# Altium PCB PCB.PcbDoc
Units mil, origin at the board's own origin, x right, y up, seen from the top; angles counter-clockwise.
Board outline 3000 x 3000 mil, 4 copper layers (Top Layer, MidLayer1, MidLayer2, Bottom Layer), stack 90 mil thick; 58 components, 28 nets, 153 pads, 23 vias.
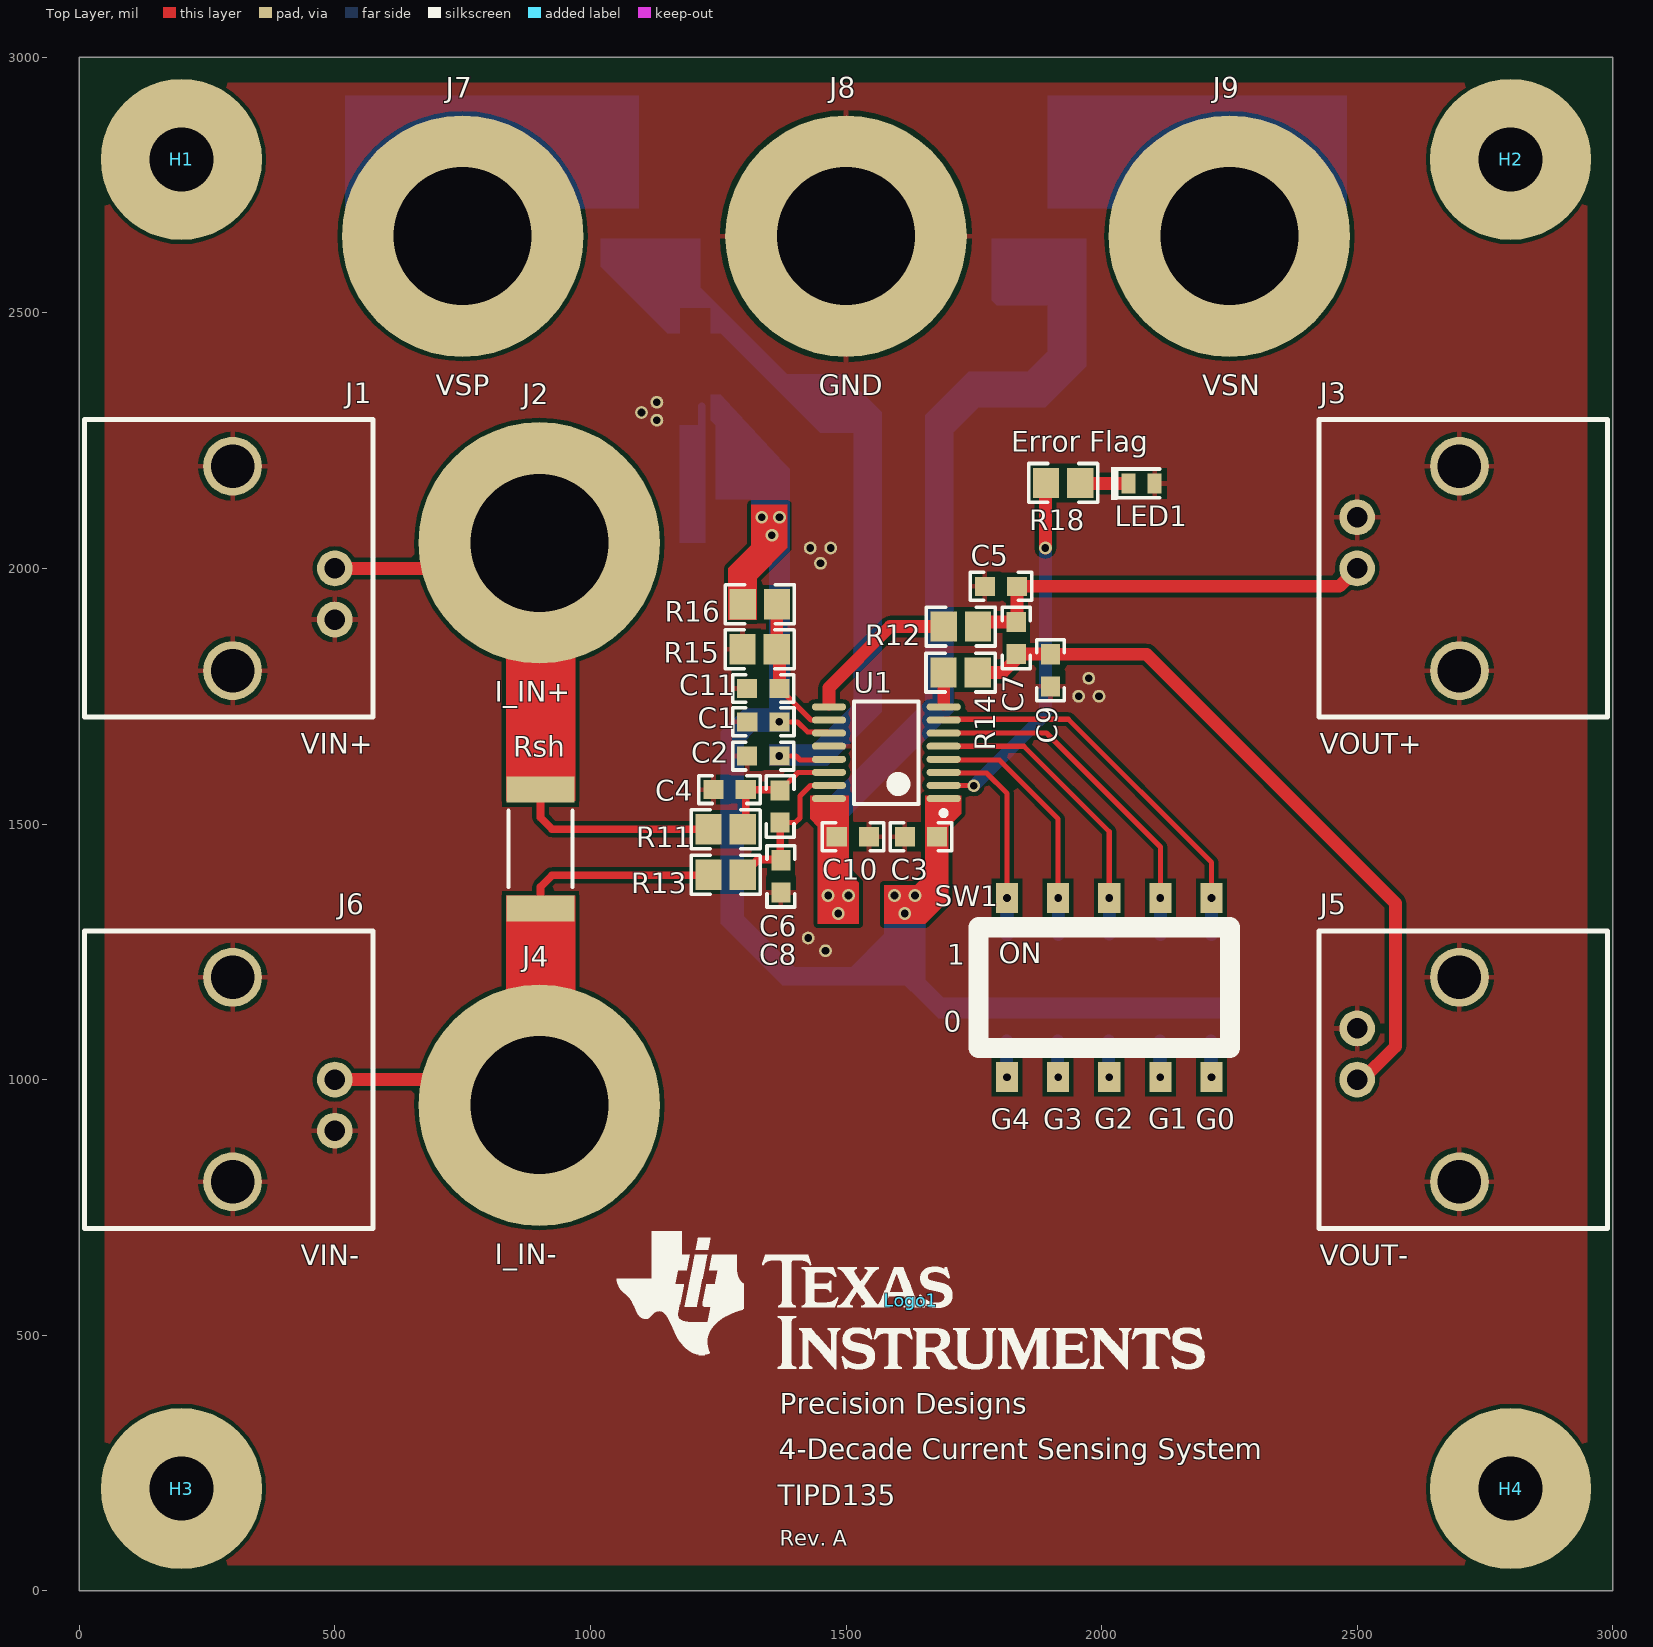
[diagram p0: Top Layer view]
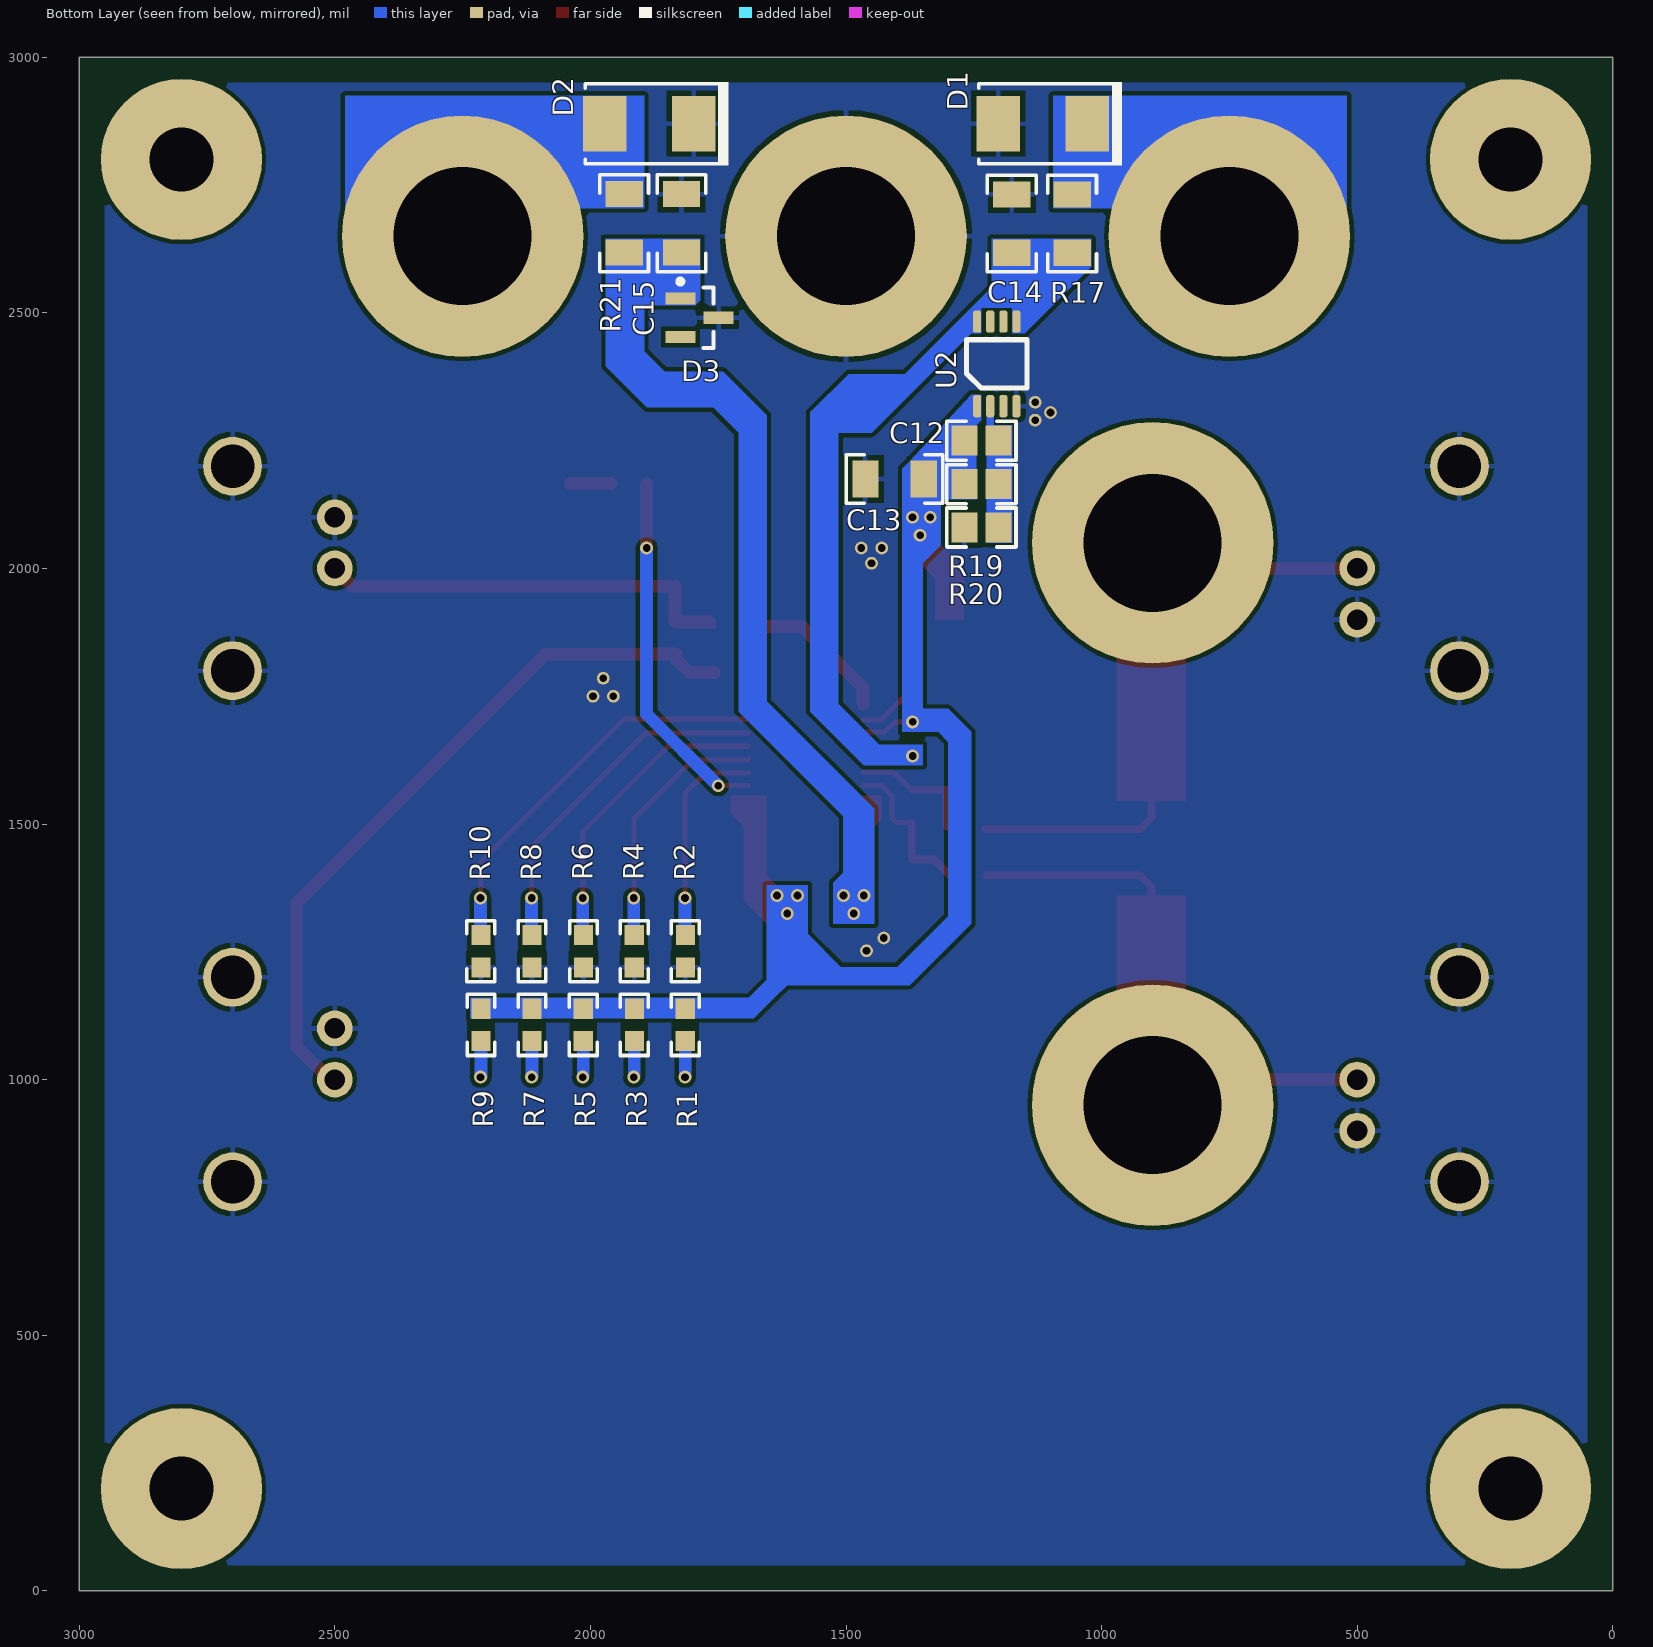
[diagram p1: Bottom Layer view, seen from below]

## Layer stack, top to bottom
Top Layer: signal copper 1.4
Dielectric: core 59.2, FR-4, Dk 4.8
MidLayer1: signal copper 1.4
Dielectric: prepreg 12.6, FR-4, Dk 4.8
MidLayer2: signal copper 1.4
Dielectric: core 12.6, FR-4, Dk 4.8
Bottom Layer: signal copper 1.4

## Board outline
0,0 3000,0 3000,3000 0,3000

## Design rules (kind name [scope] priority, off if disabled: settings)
AcuteAngle [All] p1: minimum=4.50000000000000E+0001 checktracksonly=FALSE
AssemblyTestPointUsage [All] p1: valid=2
Clearance Clearance_BoardEdge_MountingHoles [OnCopper and InComponentClass('Mounting Holes') vs IsKeepOut] p1: gap=40
Clearance Clearance_BoardEdge_Poly [OnCopper and InPoly vs IsKeepOut] p2: gap=25
Clearance Clearance_BoardEdge [OnCopper and Not InComponentClass('Logo') and not InComponentClass('FiducialMark') and not InRegion(1000,500,4000,800) vs IsKeepOut] p3: gap=75
Clearance [All] p4: gap=8
ComponentClearance ComponentClearance_Logo [InComponentClass(Logo)] p1: gap=50 collisioncheckmode=3 verticalgap=10 showdistances=FALSE
ComponentClearance ComponentClearance_ScrewToNut [(HasFootprint('NY PMS 440 0025 PH')) vs (HasFootprint('Keystone_1902C'))] p2: gap=5 collisioncheckmode=3 verticalgap=10 showdistances=FALSE
ComponentClearance ComponentClearance_MountingHoles [InComponentClass('Mounting Holes')] p3: gap=250 collisioncheckmode=3 verticalgap=100000 showdistances=FALSE
ComponentClearance ComponentClearance_SmallPassives [HasFootprint('0201*') or HasFootprint('0402*') or HasFootprint('0508') or HasFootprint('0603*') or HasFootprint('0612') or HasFootprint('0805*') or HasFootprint('0815*') or HasFootprint('0830*') or HasFootprint('1206*') or HasFootprint('1210*') or HasFootprint('1808*') or HasFootprint('1812*') or HasFootprint('1825*') or HasFootprint('2010*') or HasFootprint('2220*') or HasFootprint('2225*') or HasFootprint('2512*') or HasFootprint('2728*') or HasFootprint('3518*') vs HasFootprint('0201*') or HasFootprint('0402*') or HasFootprint('0508') or HasFootprint('0603*') or HasFootprint('0612') or HasFootprint('0805*') or HasFootprint('0815*') or HasFootprint('0830*') or HasFootprint('1206*') or HasFootprint('1210*') or HasFootprint('1808*') or HasFootprint('1812*') or HasFootprint('1825*') or HasFootprint('2010*') or HasFootprint('2220*') or HasFootprint('2225*') or HasFootprint('2512*') or HasFootprint('2728*') or HasFootprint('3518*')] p4: gap=20 collisioncheckmode=3 verticalgap=10 showdistances=FALSE
ComponentClearance ComponentClearance_THtoSMT [IsThruComponent vs IsSMTComponent] p5: gap=100 collisioncheckmode=3 verticalgap=100000 showdistances=FALSE
ComponentClearance ComponentClearance_THtoTH [IsThruComponent vs IsThruComponent] p6: gap=118.11 collisioncheckmode=3 verticalgap=100000 showdistances=FALSE
ComponentClearance [All] p7: gap=40 collisioncheckmode=3 verticalgap=10 showdistances=FALSE
DiffPairsRouting [All] p1: maxlimit=100 minlimit=10 mostfreqgap=10 maxuncoupledlength=1000
FabricationTestPointUsage TestPointUsage [All] p1: valid=2 allowmultiple=FALSE
FabricationTestpoint Testpoint [All] p1: side=3 testpointundercomponent=TRUE minsize=40 maxsize=100 preferedsize=60 minholesize=0 maxholesize=40 preferedholesize=32 testpointgrid=1 allowsidetop=TRUE allowsidebottom=TRUE usegrid=TRUE gridtolerance=0.01
FanoutControl Fanout_LCC [IsLCC] p1: bgadir=Out bgaviamode=Centered fanoutstyle=Auto fanoutdirection=Alternating viagrid=1 // Fanout_LCC (Default Rule)
FanoutControl Fanout_BGA [IsBGA] p2: bgadir=Out bgaviamode=Centered fanoutstyle=Auto fanoutdirection=Alternating viagrid=1 // Fanout_BGA (Default Rule)
FanoutControl Fanout_Default [All] p4: bgadir=Out bgaviamode=Centered fanoutstyle=Auto fanoutdirection=Alternating viagrid=1 // Fanout_Default (Default Rule)
FanoutControl Fanout_Small [(CompPinCount < 5)] p5: bgadir=Out bgaviamode=Centered fanoutstyle=Auto fanoutdirection=OutThenIn viagrid=1 // Fanout_Small (Default Rule)
HoleSize [All] p1: absolutevalues=TRUE maxlimit=300 minlimit=8 maxpercent=80.000 minpercent=20.000
MinimumAnnularRing [All] p1: minimumring=5
MinimumSolderMaskSliver MinimumSolderMaskSliver_Logo [InComponentClass('Logo') vs InComponentClass('Logo')] p1: minsoldermaskwidth=0.7
MinimumSolderMaskSliver [All] p2: minsoldermaskwidth=4
PlaneConnect [All] p1: planeconnectstyle=Relief reliefexpansion=10 reliefentries=4 reliefconductorwidth=10 reliefairgap=10
PolygonConnect "GND Vias" [(InPadClass('GND Vias') AND InNet('GND'))] p1: connectstyle=Direct reliefconductorwidth=10 reliefentries=4 polygonreliefangle="90 Angle" airgapwidth=10
PolygonConnect [All] p2: connectstyle=Relief reliefconductorwidth=10 reliefentries=4 polygonreliefangle="90 Angle" airgapwidth=10
RoutingVias [All] p1: holewidth=16 width=34 viastyle="Through Hole" minholewidth=8 minwidth=26 maxholewidth=40 maxwidth=65
SMDToCorner [All] p1: distance=30000
SilkToSilkClearance [All] p1 off: silktosilkclearance=5
SilkscreenOverComponentPads [All] p1: minsilkscreentomaskgap=5
SolderMaskExpansion [All] p1: expansion=3
Width [All] p1: maxlimit=100 minlimit=6 preferedwidth=10 checkconnectedcopper=TRUE
14 further rules are at their usual default settings.

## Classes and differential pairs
component class "Mounting Holes": H1 H2 H3 H4
component class "PGA281 SAR ADC Driver Schematic": C1 C2 C3 C4 C5 C6 C7 C8 C9 C10 C11 C12 C13 C14 C15 D1 D2 D3 J1 J2 J3 J4 J5 J6 J7 J8 J9 LED1 R1 R2 R3 R4 R5 R6 R7 R8 R9 R10 R11 R12 R13 R14 R15 R16 R17 R18 R19 R20 R21 R27 Rsh SW1 U1 U2 U3
component class Hardware_ANSI-B: H1 H2 H3 H4 Logo1
component class Logo: Logo1
pad class "GND Vias": Free-0

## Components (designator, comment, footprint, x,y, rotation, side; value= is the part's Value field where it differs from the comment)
C1 "10n" 0603 1338.23,1699.77 r0 top
C2 "10n" 0603 1338.18,1632.92 r180 top
C3 "10n" 0603 1646.79,1475.09 r0 top
C4 "1n" 0603 1272.31,1567.29 r0 top
C5 "1n" 0603 1803.26,1964.89 r0 top
C6 "10n" 0603 1371.07,1534.26 r270 top
C7 "10n" 0603 1833.02,1863.9 r270 top
C8 "1n" 0603 1372.62,1397.56 r270 top
C9 "1n" 0603 1899.98,1800.7 r270 top
C10 "10n" 0603 1513.52,1475.09 r180 top
C11 "10n" 0603 1338.16,1765.16 r180 top
C12 "10n" 0805 1235,2250 r180 bottom
C13 "10u" 1206 1405,2175 r0 bottom
C14 "10u" 1206 1175.68,2674.61 r90 bottom
C15 "10u" 1206 1821.87,2675.22 r270 bottom
D1 "SMBJ24CA" SMB 1115,2870 r0 bottom
D2 "SMBJ24CA" SMB 1885,2870 r0 bottom
D3 "BAS70-TP" DBZ0003A_N 1786.64,2490.31 r180 bottom
H1 "NY PMS 440 0025 PH" "NY PMS 440 0025 PH" 200,2800 r0 top
H2 "NY PMS 440 0025 PH" "NY PMS 440 0025 PH" 2800,2800 r0 top
H3 "NY PMS 440 0025 PH" "NY PMS 440 0025 PH" 200,200 r0 top
H4 "NY PMS 440 0025 PH" "NY PMS 440 0025 PH" 2800,200 r0 top
J1 "VIN+" "Right Angle BNC" 500,2000 r90 top
J2 "I_IN+" Johnson_108-0740-001 900,2050 r0 top
J3 "VOUT+" "Right Angle BNC" 2500,2000 r270 top
J4 "I_IN-" Johnson_108-0740-001 900,950 r0 top
J5 "VOUT-" "Right Angle BNC" 2500,1000 r270 top
J6 "VIN-" "Right Angle BNC" 500,1000 r90 top
J7 "VSP" Johnson_108-0740-001 750,2650 r0 top
J8 "GND" Johnson_108-0740-001 1500,2650 r0 top
J9 "VSN" Johnson_108-0740-001 2250,2650 r0 top
LED1 "LTST-C190CKT" Diode_0603 2078.11,2166.17 r0 top
Logo1 "Texas Instruments" TI_Stacked_Overlay_Medium 1626.78,568.73 r0 top
R1 "Used in BOM report" 0603 1814.36,1107.11 r270 bottom
R2 "Used in BOM report" 0603 1814.32,1251.11 r270 bottom
R3 "Used in BOM report" 0603 1914.08,1107.11 r270 bottom
R4 "Used in BOM report" 0603 1914.34,1251.11 r270 bottom
R5 "Used in BOM report" 0603 2014.08,1107.11 r270 bottom
R6 "Used in BOM report" 0603 2013.5,1251.11 r270 bottom
R7 "Used in BOM report" 0603 2114.32,1107.11 r270 bottom
R8 "Used in BOM report" 0603 2114.36,1251.11 r270 bottom
R9 "Used in BOM report" 0603 2214.08,1107.11 r270 bottom
R10 "Used in BOM report" 0603 2214.38,1251.11 r270 bottom
R11 "Used in BOM report" 0805 1264.55,1489.72 r0 top
R12 "Used in BOM report" 0805 1724.66,1886.28 r0 top
R13 "Used in BOM report" 0805 1264.55,1400.76 r0 top
R14 "Used in BOM report" 0805 1724.14,1796.3 r0 top
R15 "Used in BOM report" 0805 1331.1,1842.01 r0 top
R16 "Used in BOM report" 0805 1331.54,1930 r0 top
R17 "Used in BOM report" 1206 1057.56,2674.61 r270 bottom
R18 "Used in BOM report" 0805 1924.92,2167.18 r0 top
R19 "Used in BOM report" 0805 1235,2165 r0 bottom
R20 "Used in BOM report" 0805 1235,2080 r0 bottom
R21 "Used in BOM report" 1206 1933.93,2675.22 r270 bottom
Rsh "Used in BOM report" 2512 902.43,1451.11 r90 top
SW1 "Used in BOM report" A6S-5104-H 2015,1180 r90 top
U1 "PGA281" PW0016A_N 1578.88,1639.39 r180 top
U2 "TPS7A4101" dgk-8 1205,2400 r90 bottom

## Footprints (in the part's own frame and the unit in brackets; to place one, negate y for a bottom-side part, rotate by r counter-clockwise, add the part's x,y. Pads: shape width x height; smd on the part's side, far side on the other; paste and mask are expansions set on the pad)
0603 [mm] "0603 from SM-752 data"
  rect 1x0.95 smd: 1(-0.8,0) 2(0.8,0)
  silkscreen extent -1.52,-0.69 1.52,0.69, body extent -0.87,-0.47 0.87,0.47, height 0.85
0805 [mm] "0805 from SM-752 data"
  rect 1.3x1.5 smd: 1(-0.85,0) 2(0.85,0)
  silkscreen extent -1.72,-0.97 1.72,0.97, body extent -1.1,-0.72 1.1,0.72, height 1.1
1206 [mm] "1206 from SM-752 data"
  rect 1.3x1.85 smd: 1(-1.45,0) 2(1.45,0)
  silkscreen extent -2.4,-1.21 2.4,1.21, body extent -1.7,-0.9 1.7,0.9, height 1.35
2512 [mm] "Chip Resistor, Body 6.3x3.2mm, IPC Medium Density"
  rect 1.3x3.4 smd: 1(-2.95,0) 2(2.95,0)
  silkscreen extent -1.9,-1.6 1.9,1.6, body extent -3.22,-1.67 3.22,1.67, height 0.71
A6S-5104-H [mm]
  rect 1.5x1.1 smd: 1(-4.45,5.08) 2(-4.45,2.54) 3(-4.45,0) 4(-4.45,-2.54) 5(-4.45,-5.08) 6(4.45,-5.08) 7(4.45,-2.54) 8(4.45,0) 9(4.45,2.54) 10(4.45,5.08)
  silkscreen extent -3,-6 3,6.5
DBZ0003A_N [mm] "SOT23, 3-Leads, Body 2.9x1.3mm, Pitch 0.95mm, Lead Span 2.4mm, IPC Medium Density"
  rect 1.5x0.6 smd: 1(-0.95,0.95) 2(-0.95,-0.95) 3(0.95,0)
  silkscreen extent -1.07,-1.5 0.7,1.92, body extent -0.7,-1.52 0.7,1.52, height 1.12
dgk-8 [mm] "MSOP-8, SMD, 0.65mm PITCH"
  rrect50% 1.1x0.4 smd mask+0.05: 1(-2.1,0.975) 2(-2.1,0.325) 3(-2.1,-0.325) 4(-2.1,-0.975) 5(2.1,-0.975) 6(2.1,-0.325) 7(2.1,0.325) 8(2.1,0.975)
  silkscreen extent -1.2,-1.5 1.2,1.5
Diode_0603 [mm] "Based on Bourns recommended land pattern Rev 10/09"
  rect 0.7x1 smd: 1(-0.65,0) 2(0.65,0)
  silkscreen extent -1.5,-0.8 0.9,0.8, body extent -0.9,-0.5 0.9,0.5, height 0.85
Johnson_108-0740-001 [mm] "Banana Jack Uninsulated Standard Type"
  round 12 hole 6.858: 1(0,0)
  body extent -4.77,-5.43 4.75,5.57, height 2.39
"NY PMS 440 0025 PH" [mm] "4-40 nylon screw and mounting hole"
  round 8 hole 3.2: 1(0,0)
  body extent -3.3,-3.3 3.3,3.3, height 2.69
PW0016A_N [mm] "TSOP, 16-Leads, Body 5x4.4mm, Pitch 0.65mm, IPC Medium Density"
  oval 1.7x0.35 smd: 1(-2.85,2.275) 2(-2.85,1.625) 3(-2.85,0.975) 4(-2.85,0.325) 5(-2.85,-0.325) 6(-2.85,-0.975) 7(-2.85,-1.625) 8(-2.85,-2.275) 9(2.85,-2.275) 10(2.85,-1.625) 11(2.85,-0.975) 12(2.85,-0.325) 13(2.85,0.325) 14(2.85,0.975) 15(2.85,1.625) 16(2.85,2.275)
  silkscreen extent -2.98,-2.55 1.6,3.12, body extent -2.25,-2.55 2.25,2.55, height 1.2
"Right Angle BNC" [mil]
  round 70 hole 40: 1(0,0) 2(-100,0)
  round 115 hole 85: 3(200,200) 4(-200,200)
  silkscreen extent -291,-75 291,490, body extent -290,-50 291,1325, height 519
SMB [mil] "Molded Diode, 2-Leads, Body 5.4x3.6mm, IPC Medium Density, based on OnSemi component dimensions"
  rect 85x107.99 smd: 1(-87.01,0) 2(87.01,0)
  silkscreen extent -155,-82 125,82, body extent -106,-71 106,71, height 91
TI_Stacked_Overlay_Medium [mil]
  silkscreen extent -576,-136 576,134

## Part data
C1 C2 C3 C4 C5 C6 C7 C8 C9 C10 C11 C12 C13 C14 C15: library part Capacitor, "CAP, CERM, xxxF, xxV, [TempCo], xx%, [PackageReference]"
D1 D2: library part TVS_BI_SMB
H1 H2 H3 H4: "Machine Screw, Round, #4-40 x 1/4, Nylon, Philips panhead"
J1 J3 J5 J6: library part "BNC Right Angle"
J2 J4 J7 J8 J9: library part 108-0740-001, "Standard Banana Jack, Uninsulated, 15A"
LED1: library part LED, "LED, [Color], [MountType]"
Logo1: library part TI_Logo, "Texas Instrument Corporate Signature"
R1 R2 R3 R4 R5 R6 R7 R8 R9 R10 R11 R12 R13 R14 R15 R16 R17 R18 R19 R20 R21 Rsh: library part Resistor, "RES, xxx ohm, x%, xW, [PackageReference]"
SW1: library part SWITCH_5xSPST

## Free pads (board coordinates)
  round 25 hole 15: 0(1100,2305) 0(1130,2290) 0(1130,2325) 0(1426,1277) 0(1430,2040) 0(1450,2010) 0(1460,1252) 0(1470,2040) 0(1955,1750) 0(1975,1785) 0(1995,1750)

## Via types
v1: diameter 25, hole 15, Top Layer to Bottom Layer, 23 vias

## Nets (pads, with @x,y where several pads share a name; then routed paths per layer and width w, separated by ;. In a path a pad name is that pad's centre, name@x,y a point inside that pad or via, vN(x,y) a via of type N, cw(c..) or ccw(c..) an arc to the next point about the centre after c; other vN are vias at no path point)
/EF: R18.1 U1.2 | length 709.9
  Top Layer w10: U1.2 1749.59,1575.41 v1(1750,1575) ; R18.1@1890,2165.72 R18.1
  Top Layer w25: v1(1890,2040) R18.1@1890,2165.72
  Bottom Layer w25: v1(1750,1575) 1890,1715 v1(1890,2040)
G0: R10.1 SW1.6 U1.7 | length 783.2
  Top Layer w10: U1.7 1692.72,1705 1935,1705 2215,1425 v1(2215,1355.2)
  Bottom Layer w10: R10.1 R10.1@2215,1283.23
  Bottom Layer w25: R10.1@2215,1283.23 v1(2215,1355.2)
G1: R8.1 SW1.7 U1.6 | length 688.8
  Top Layer w10: U1.6 1892.23,1677.77 2115,1455 v1(2115,1355.2)
  Bottom Layer w10: R8.1 R8.1@2115,1283.25
  Bottom Layer w25: R8.1@2115,1283.25 v1(2115,1355.2)
G2: R6.1 SW1.8 U1.5 | length 596.2
  Top Layer w10: U1.5 1847.82,1652.18 2015,1485 v1(2015,1355.2)
  Bottom Layer w10: R6.1 R6.1@2015,1284.11
  Bottom Layer w25: R6.1@2015,1284.11 v1(2015,1355.2)
G3: R4.1 SW1.9 U1.4 | length 499.9
  Top Layer w10: U1.4 1692.68,1625 1800,1625 1915,1510 v1(1915,1355.2)
  Bottom Layer w10: R4.1 R4.1@1915,1283.27
  Bottom Layer w25: R4.1@1915,1283.27 v1(1915,1355.2)
G4: R2.1 SW1.10 U1.3 | length 418.6
  Top Layer w10: U1.3 1692.09,1600 1775,1600 1815,1560 v1(1815,1355.2)
  Bottom Layer w10: R2.1 R2.1@1815,1283.29
  Bottom Layer w25: R2.1@1815,1283.29 v1(1815,1355.2)
GND: C1.1 C2.2 C3.1 C4.1 C5.1 C8.2 C9.2 C10.1 C11.2 C13.2 C14.2 C15.1 D1.2 D2.1 D3.3 J1.2 J1.3 J1.4 J3.2 J3.3 J3.4 J5.2 J5.3 J5.4 J6.2 J6.3 J6.4 J8.1 LED1.2 pad.0 R2.2 R4.2 R6.2 R8.2 R10.2 R15.1 R20.2 U1.12 U2.4
NetC4_2: C4.2 C6.1 R11.2 U1.14 | length 258.1
  Top Layer w10: R11.2 R11.2@1303.81,1495.51 ; C6.1@1369.54,1567.29 C6.1 1406.31,1601 U1.14
  Top Layer w15: R11.2@1303.81,1495.51 C4.2 C6.1@1369.54,1567.29
NetC5_2: C5.2 C7.1 J3.1 R12.2 | length 828.7
  Top Layer w10: R12.2 R12.2@1767.23,1895.4 ; C7.1 C7.1@1834.76,1897.14
  Top Layer w25: R12.2@1767.23,1895.4 C7.1 ; C7.1@1834.76,1897.14 C5.2 2464.89,1964.89 J3.1
NetC6_2: C6.2 C8.1 R13.2 U1.15 | length 308.5
  Top Layer w10: C6.2 1400.84,1502.77 1410,1511.93 1410,1555 1430.41,1575.41 U1.15
  Top Layer w15: R13.2 1327.86,1430.6 1371.07,1430.6 C6.2
NetC7_2: C7.2 C9.1 J5.1 R14.2 | length 1425.8
  Top Layer w10: C9.1@1899.77,1832.4 C9.1 ; J5.1 J5.1@2505,995
  Top Layer w25: R14.2 1806.3,1796.3 1833.02,1823.02 C7.2 C9.1@1899.77,1832.4 ; C9.1 2087.81,1832.19 2575,1345 2575,1065 J5.1@2505,995
NetC11_1: C11.1 R15.2 R16.2 U1.10 | length 290
  Top Layer w10: R15.2 1364.56,1825.44 R15.2@1370,1820 ; R16.2@1364.56,1929.56 R16.2 ; C11.1@1370,1765.51 C11.1 1431.46,1703.36 U1.10
  Top Layer w25: R15.2 R16.2@1364.56,1929.56 ; C11.1@1370,1765.51 R15.2@1370,1820
NetC12_2: C12.2 R19.1 R20.1 U2.2 | length 74.1
  Bottom Layer w10: C12.2 C12.2@1217.8,2266.26
  Bottom Layer w15: C12.2@1217.8,2266.26 U2.2
NetD1_1: D1.1 J7.1 R17.1
NetD2_2: D2.2 J9.1 R21.1
NetJ1_1: J1.1 J2.1 R11.1 Rsh.2 | length 810
  Top Layer w10: J2.1@850,2000 J2.1
  Top Layer w15: Rsh.2 902.43,1512.57 925,1490 R11.1@1227.69,1490
  Top Layer w25: J1.1 J2.1@850,2000
NetJ4_1: J4.1 J6.1 R13.1 Rsh.1 | length 814.1
  Top Layer w10: J4.1@850,1000 J4.1 ; Rsh.1 Rsh.1@913.26,1324.14 ; R13.1@1224.92,1400 R13.1@1227.63,1397.3
  Top Layer w15: Rsh.1 902.43,1377.43 925,1400 R13.1@1224.92,1400
  Top Layer w25: J6.1 J4.1@850,1000
NetLED1_1: LED1.1 R18.2 | length 81
  Top Layer w10: R18.2 R18.2@1959.39,2166.17
  Top Layer w25: R18.2@1959.39,2166.17 LED1.1@2039,2166.17
NetR1_2: R1.2 SW1.1 | length 71.1
  Bottom Layer w10: v1@1814.36,1005.44 v1(1815,1004.8)
  Bottom Layer w25: v1@1814.36,1005.44 R1.2
NetR3_2: R3.2 SW1.2 | length 71.2
  Bottom Layer w10: v1@1914.08,1005.72 v1(1915,1004.8)
  Bottom Layer w25: v1@1914.08,1005.72 R3.2
NetR5_2: R5.2 SW1.3 | length 71.2
  Bottom Layer w10: v1@2014.08,1005.72 v1(2015,1004.8)
  Bottom Layer w25: v1@2014.08,1005.72 R5.2
NetR7_2: R7.2 SW1.4 | length 71.1
  Bottom Layer w10: v1@2114.32,1005.48 v1(2115,1004.8)
  Bottom Layer w25: v1@2114.32,1005.48 R7.2
NetR9_2: R9.2 SW1.5 | length 71.2
  Bottom Layer w10: v1@2214.08,1005.72 v1(2215,1004.8)
  Bottom Layer w25: v1@2214.08,1005.72 R9.2
NetR12_1: R12.1 U1.9 | length 305.7
  Top Layer w25: U1.9@1466.68,1735 1466.68,1766.68 1586.28,1886.28 R12.1
NetR14_1: R14.1 U1.8 | length 61.5
  Top Layer w10: R14.1 R14.1@1691.09,1795.88
  Top Layer w25: U1.8@1691.09,1735 R14.1@1691.09,1795.88
VSN: C10.2 C15.2 D3.1 R21.2 U1.16 | length 193.2
  Top Layer w10: U1.16 1466.68,1528.32 1480,1515 1480,1477.11 C10.2
  Bottom Layer w50: C15.2 R21.2
  other v1: 1485,1325 1465,1360 1505,1360
VSOP: C1.2 C3.2 C12.1 C13.1 R1.1 R3.1 R5.1 R7.1 R9.1 R16.1 R19.2 U1.1 U1.11 U2.1 | length 585.8
  Top Layer w10: v1(1369.73,1699.77) 1405.23,1699.77 1425,1680 1464.45,1680 U1.11 ; C3.2 1680,1476.8 1680,1520 1691.09,1531.09 U1.1
  Bottom Layer w25: R1.1 R3.1 R5.1 R7.1 R9.1
  other v1: 1615,1325 1595,1360 1635,1360 1355,2065 1335,2100 1370,2100
VSP: C2.1 C14.1 R17.2 U1.13 U2.5 U2.8 | length 219.1
  Top Layer w10: v1(1369.68,1632.92) 1402.08,1632.92 1410,1625 1465.09,1625 U1.13
  Bottom Layer w50: R17.2 C14.1
pads on no net: D3.2 H1.1 H2.1 H3.1 H4.1 U2.3 U2.6 U2.7

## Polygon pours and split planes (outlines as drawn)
GND on Top Layer "Bottom Layer-No Net" (solid, remove dead copper, pour order 6): 50,50 2950,50 2950,2950 50,2950
GND on Bottom Layer "Bottom Layer-No Net 1" (solid, remove dead copper, pour order 8): 50,50 2950,50 2950,2950 50,2950

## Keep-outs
Keep-Out Layer:
  text ".Layer_Name" at 577,-858.49 h30

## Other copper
Top Layer:
  region net VSN: 1525,1305 1525,1385 1505,1405 1505,1555 1430,1555 1430,1510 1445,1495 1445,1305
  region net VSOP: 1655,1495 1655,1555 1725,1555 1725,1520 1700,1495
  region net VSOP: 1575,1380 1635,1380 1655,1400 1655,1495 1700,1495 1700,1350 1655,1305 1575,1305
  region net VSOP: 1270,1900 1325,1900 1325,1980 1385,2040 1385,2125 1315,2125 1315,2045 1270,2000
  region net NetJ4_1: 835,1360 970,1360 970,1135 835,1135
  region net NetJ1_1: 835,1545 970,1545 970,1830 835,1830
Bottom Layer:
  region net VSOP: 1655,1305 1655,1195 1600,1250
  region net VSOP: 1575,1225 1680,1120 2235,1120 2235,1160 1690,1160 1600,1250 1590,1250 1590,1240
  region net VSOP: 1319.88,1680 1300,1660.12 1300,1320 1400,1220 1510,1220 1575,1285 1575,1380 1655,1380 1655,1305 1615,1185 1375,1185 1255,1305 1255,1680 1300,1725 1390,1725 1390,1680
  region net VSN: 1445,1385 1445,1530 1655,1740 1655,2300 1740,2385 1855,2385 1895,2425 1895,2645 1970,2645 1970,2395 1890,2315 1760,2315 1710,2265 1710,1720 1505,1515 1505,1405 1525,1385
  region net VSN: 1445,1305 1525,1305 1525,1385 1445,1385
  region net VSP: 1495,2380 1570,2305 1570,2265 1450,2265 1335,2380
  region net VSP: 1350,1655 1435,1655 1515,1735 1515,2285 1520,2280 1570,2280 1570,1720 1465,1615 1350,1615
  region net VSP: 1350,1615 1350,1655 1390,1655 1390,1615
  region net VSP: 1255,2510 1470,2295 1570,2295 1570,2265 1450,2265 1250,2465 1250,2510
  region net VSOP: 1315,2045 1350,2010 1350,1680 1390,1680 1390,2195 1385,2200 1315,2130
  region net VSOP: 1375,2210 1385,2200 1385,2045 1315,2045 1315,2210
  region net VSOP: 1235,2340 1235,2290 1245,2280 1245,2135 1375,2135 1375,2210 1255,2340
  region net NetC12_2: 1175,2280 1225,2280 1225,2050 1175,2050
  region net VSP: 1235,2510 1235,2460 1255,2460 1255,2510 1215,2550 1175,2510
  region net VSP: 1175,2460 1175,2510 1215,2550 1215,2645 1020,2645 1020,2590 1150,2460
  region net VSN: 1795,2515 1785,2525 1785,2645 1970,2645 1970,2590 1895,2515
  region net NetD2_2: 1895,2705 1895,2925 2480,2925 2480,2705
  region net NetD1_1: 520,2925 1095,2925 1095,2705 520,2705

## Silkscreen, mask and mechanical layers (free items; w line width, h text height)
Top Overlay:
  text "Error Flag" at 1823,2228 h40
  text "1" at 1697.77,1224.27 h40
  text "0" at 1690.86,1093.19 h40
  text "G2" at 1985.63,904.31 h40
  text "G1" at 2091.09,903.78 h40
  text "G4" at 1783.2,903.25 h40
  text "G3" at 1886.01,903.25 h40
  text "G0" at 2184.36,903.25 h40
  text "Precision Designs" at 1370.87,346.16 h40
  text "4-Decade Current Sensing System" at 1367.99,257.02 h40
  text "TIPD135" at 1366.97,166.83 h40
  text "Rev. A" at 1370.56,87.96 h30
Top Paste:
  text ".Layer_Name" at 577,-858.49 h30
Bottom Paste:
  text ".Layer_Name" at 577,-858.49 h30
Top Solder:
  text ".Layer_Name" at 577,-858.49 h30
  text ".Layer_Name" at 577,-858.49 h30
Bottom Solder:
  text ".Layer_Name" at 577,-858.49 h30
Drill Guide:
  text ".Layer_Name" at 577,-858.49 h30
M1 Board Outline:
  the board outline again, w10
M2 Board Dimensions:
  rectangle: 124.5,-410.5 499.5,-285.5
  rectangle: -0.5,-285.5 124.5,-160.5
  lines w7: -0.5,-285.5 999.5,-285.5 ; 124.5,-410.5 124.5,-160.5 ; 249.5,-410.5 249.5,-160.5 ; 499.5,-410.5 499.5,-160.5 ; 749.5,-410.5 749.5,-160.5 ; -0.5,-410.5 -0.5,-160.5 999.5,-160.5 999.5,-410.5 -0.5,-410.5
  lines w10: -0.5,-475.5 -0.5,-455.5 ; 59.5,-485.5 -0.5,-465.5 ; 59.5,-445.5 -0.5,-465.5 ; 223.58,-465.5 -0.5,-465.5 ; 775.42,-465.5 999.5,-465.5 ; 939.5,-485.5 999.5,-465.5 ; 939.5,-445.5 999.5,-465.5 ; 999.5,-475.5 999.5,-455.5
  text "1000 (mil)" at 233.58,-501.49 h60
M3 3D STEP Top:
  text ".Layer_Name" at 577,-858.49 h30
M4 3D STEP Bottom:
  text ".Layer_Name" at 577,-858.49 h30
M5 Assembly Top:
  lines w10: -292,-930.17 6308,-930.17 ; -292,-726.83 6310,-726.83 ; -292,-523.5 -292,-1133.5 3713,-1133.5 6310,-1133.5 6310,-523.5 -291.5,-523.5 -291.5,-1133.5 1284,-1133.5 ; 2173,-1133.5 2173,-523.5 ; 3440,-726.83 3440,-523.5 ; 4280,-726.83 4280,-523.5 ; 4902,-1140 4902,-937.17
  text "COMPONENTS MARKED 'DNP' SHOULD NOT BE POPULATED, AND MAY NOT BE IN BILL OF MATERIALS" at 1153.5,-318.5 h30
  text "ASSEMBLY VARIANT:" at 1153,-434 h30
  text ".VariantName" at 2189,-434 h30
  text "PCB VIEWED FROM TOP SIDE" at -228.5,-655.67 h30
  text "BOARD #:" at 2248,-655.67 h30
  text ".PRJ_Number" at 2793.5,-655.67 h30
  text "REV:" at 3638,-655.67 h30
  text ".PCB_Rev" at 3929.5,-655.67 h30
  text "SVN REV:" at 4476,-655.67 h30
  text ".VersionControl_RevNumber" at 4982,-655.67 h30
  text "IGNORE ->" at -228.5,-858.49 h30
  text "PLOT NAME =" at -228.5,-1064.34 h30
  text ".plot_File_Name" at 577,-1064.34 h30
  text "GENERATED    :" at 2250,-1064.34 h30
  text ".Print_Date" at 3119.5,-1064.34 h30
  text ".Print_Time" at 3848.5,-1064.34 h30
  text "TEXAS INSTRUMENTS" at 5113,-1064.34 h30
M6 Assembly Bottom:
  lines w10: -292.5,-727.33 6309.5,-727.33 ; -290.5,-930.67 6309.5,-930.67 ; 1115.5,-1140.5 1115.5,-937.67 ; 1737.5,-727.33 1737.5,-524 ; 2577.5,-727.33 2577.5,-524 ; 3844.5,-1134 3844.5,-524 ; 4733.5,-1134 6309,-1134 6309,-524 -292.5,-524 -292.5,-1134 2304.5,-1134 6309.5,-1134 6309.5,-524 ; 963,2590 963,2709.06 963.94,2710 1049,2710 1057.24,2701.76 1057.24,2591 1056.24,2590 963,2590
  text "COMPONENTS MARKED 'DNP' SHOULD NOT BE POPULATED, AND MAY NOT BE IN BILL OF MATERIALS" at 6102,-318 h30
  text ".VariantName" at 5058,-434 h30
  text "ASSEMBLY VARIANT:" at 6097,-434 h30
  text ".VersionControl_RevNumber" at 1035.5,-656.17 h30
  text "SVN REV:" at 1541.5,-656.17 h30
  text ".PCB_Rev" at 2088,-656.17 h30
  text "REV:" at 2379.5,-656.17 h30
  text ".PRJ_Number" at 3224,-656.17 h30
  text "BOARD #:" at 3769.5,-656.17 h30
  text "PCB VIEWED FROM BOTTOM SIDE" at 6246,-656.17 h30
  text "IGNORE ->" at 2547.85,-858.49 h30
  text "TEXAS INSTRUMENTS" at 904.5,-1064.84 h30
  text ".Print_Time" at 2169,-1064.84 h30
  text ".Print_Date" at 2898,-1064.84 h30
  text "GENERATED    :" at 3767.5,-1064.84 h30
  text ".plot_File_Name" at 5440.5,-1064.84 h30
  text "PLOT NAME =" at 6246,-1064.84 h30
M9 Title Sheet:
  drawing of 57 lines, arcs and shapes, not listed
  text "1" at 739.84,8036.5 h30
  text "2" at 3235.5,8036.5 h30
  text "3" at 5724.84,8036.5 h30
  text "4" at 8231.51,8036.5 h30
  text "5" at 10730.5,8036.5 h30
  text "6" at 13235.5,8036.5 h30
  text "A" at -416.5,6893.5 h30
  text "A" at 14383.5,6893.5 h30
  text "B" at -416.5,4513.5 h30
  text "B" at 14383.5,4513.5 h30
  text "C" at -416.5,2138.5 h30
  text "C" at 14383.5,2138.5 h30
  text "PROJECT TITLE:" at 11343.5,277.5 h30
  text ".PRJ_Title" at 11393.5,144.17 h30
  text "DESIGNED FOR:" at 11343.5,-23.5 h30
  text ".PRJ_Customer" at 11393.5,-163.5 h30
  text "D" at -416.5,-231.5 h30
  text "D" at 14383.5,-231.5 h30
  text "FILE NAME:" at 11343.5,-323.5 h30
  text ".PCB_File_Name_No_Path" at 11393.5,-443.5 h30
  text "Texas Instruments (TI) and/or its licensors do not warrant the accuracy or completeness of this specification" at 6374,-605.34 h30
  text "ENGINEER:" at 11343.5,-613.5 h30
  text "LAYOUT BY:" at 12848.5,-613.5 h30
  text "or any information contained therein. TI and/or its licensors do not warrant that this design will meet" at 6329.01,-718 h30
  text ".PRJ_Engineer" at 11393.5,-768.49 h30
  text ".PCB_Layout" at 12899,-768.49 h30
  text "the specifications, will be suitable for your application or fit for any particular purpose, or will operate in" at 6329.01,-830.67 h30
  text ".Layer_Name" at 577,-858.49 h30
  text "ALTIUM DESIGNER VERSION:" at 12848.5,-923.5 h30
  text "an implementation. TI and/or its licensors do not warrant that the design is production worthy. You should" at 6329.01,-943.33 h30
  text "completely validate and test your design implementation to confirm the system functionality for your application." at 6374,-1056 h30
  text ".print_Scale" at 11393.5,-1056.83 h30
  text ".Application_BuildNumber" at 12899,-1056.83 h30
  text "1" at 739.84,-1263.5 h30
  text "2" at 3235.5,-1263.5 h30
  text "3" at 5724.84,-1263.5 h30
  text "4" at 8231.51,-1263.5 h30
  text "5" at 10730.5,-1263.5 h30
  text "6" at 13235.5,-1263.5 h30
M10 Fab Notes:
  drawing of 203 lines, arcs and shapes, not listed
  text "DESIGN INFORMATION" at 12381.02,6810 h30
  text "(REFER ALSO ARRAY/PANEL PROFILING INFORMATION)" at 12019.46,6648.29 h30
  text "BOARD SIZE" at 11333.46,6644 h30
  text "3450MIL" at 11795.78,6516.18 h30
  text "X" at 12301.46,6516.18 h30
  text "4950MIL" at 12532.78,6516.18 h30
  text "Number of Layers :" at 11736.46,6319 h30
  text "2" at 12831.27,6309 h30
  text "MIN. TRACK WIDTH:" at 11736.46,6180 h30
  text "8" at 12832.7,6180 h30
  text "MIL" at 12987.46,6180 h30
  text "MIN. CLEARANCE:" at 11736.46,6048 h30
  text "8" at 12832.7,6048 h30
  text "MIL" at 12987.46,6048 h30
  text "MIN. VIA PAD SIZE:" at 11736.46,5916 h30
  text "24" at 12802.71,5916 h30
  text "MIL" at 12987.46,5916 h30
  text "0.05mm (2MIL)" at 12431.46,5774.29 h30
  text "MINIMUM ANNULAR RING" at 11407.23,5770 h30
  text "EXTERNAL" at 13139.46,5770 h30
  text "PER" at 11607.23,5652 h30
  text "IPC-D-275 CLASS 2 LEVEL C" at 11827.23,5652 h30
  text "MIL, HOLES" at 13315.46,5539.71 h30
  text "+/-" at 12923,5539 h30
  text "+/-" at 13777,5539 h30
  text "REGISTRATION TOLERANCES:" at 11407.23,5534 h30
  text "METAL" at 12607,5534 h30
  text "5" at 13183.2,5534 h30
  text "3" at 14016.2,5534 h30
  text "MIL" at 14132.46,5534 h30
  text "MATERIAL:" at 11332.46,5324.54 h30
  text "FR-4 High Tg" at 12318.9,5184.21 h30
  text "FR-4" at 11793.46,5175.64 h30
  text "X" at 12165.46,5175.64 h30
  text "OTHER" at 13241.46,5175.64 h30
  text "62 MIL (1.6mm) +/-10%" at 12073.56,5012.92 h30
  text "THICKNESS:" at 11407.23,5008.64 h30
  text "X" at 11945.4,5008.64 h30
  text "OTHER" at 13358.46,5008.64 h30
  text "TOLERANCE:" at 11407.23,4850.64 h30
  text "X" at 12246.53,4850.64 h30
  text "ANSI IPC-6012 TYPE 3 CLASS 2" at 12433.48,4850.64 h30
  text "OTHER +/-" at 12433.46,4694.64 h30
  text "BOW & TWIST:" at 11407.23,4537.64 h30
  text "X" at 12246.53,4537.64 h30
  text "ANSI IPC-6012 TYPE 3 CLASS 2" at 12433.48,4537.64 h30
  text "OTHER +/-" at 12433.46,4379.13 h30
  text "COPPER THICKNESS (FINISHED):" at 11332.46,4243.64 h30
  text "1.4MIL (1oz)" at 12212.46,4090.92 h30
  text "2MIL (1.4oz)" at 12979.46,4090.92 h30
  text "2.8MIL (2oz)" at 13706.46,4090.92 h30
  text "OUTER:" at 11689.46,4086.64 h30
  text "X" at 12084,4086 h30
  text "1.4MIL (1oz)" at 12562.46,3933.92 h30
  text "2.8MIL (2oz)" at 13406.46,3933.92 h30
  text "INNER SIGNAL:" at 11689.46,3929.64 h30
  text "X" at 12435.42,3929.64 h30
  text "DRILLING:" at 11332.46,3790.64 h30
  text "REFERENCE:" at 11407.23,3673.64 h30
  text "X" at 12055.46,3673.64 h30
  text "AS SHOWN" at 12242.46,3673.64 h30
  text "X" at 12956.46,3673.64 h30
  text "NC_DRILL FILES" at 13093.46,3673.64 h30
  text "PTH MIN COPPER THICKNESS:" at 11407.23,3515.64 h30
  text "X" at 12757.46,3515.64 h30
  text "1MIL" at 12894.46,3515.64 h30
  text "OTHER" at 13391.46,3515.64 h30
  text "BOARD FINISH:" at 11332.46,3356.64 h30
  text "SILKSCREEN:" at 11487.68,3238.64 h30
  text "X" at 12436.46,3238.64 h30
  text "TOP" at 12562.46,3238.64 h30
  text "X" at 12946.46,3238.64 h30
  text "BOTTOM" at 13073.46,3238.64 h30
  text "SILKSCREEN COLOR:" at 11487.68,3071.64 h30
  text "X" at 12435.42,3071.64 h30
  text "WHITE" at 12562.46,3071.64 h30
  text "OTHER" at 13073.46,3071.64 h30
  text "SOLDER RESIST COLOR:" at 11487.68,2901.64 h30
  text "X" at 12055.42,2742.44 h30
  text "GREEN" at 12182.46,2742.44 h30
  text "BLUE" at 12773.46,2742.44 h30
  text "OTHER" at 13311.46,2742.44 h30
  text "IMMERSION GOLD (ENIG)" at 12393.46,2553.92 h30
  text "SURFACE FINISH:" at 11332.46,2549.64 h30
  text "X" at 12206.51,2549.64 h30
  text "Pb-FREE HASL" at 13625.75,2549.64 h30
  text "OTHER" at 12393.46,2392.64 h30
  text "ARRAY/PANEL:" at 11332.46,2213.64 h30
  text "CUT AND TRIM PER MECH LAYER 1" at 12393.46,2209.35 h30
  text "N.C. ROUTE" at 12393.46,2057.64 h30
  text "X" at 13072.46,2057.64 h30
  text "V. SCORE" at 13259.46,2057.64 h30
  text "CERTIFICATION:" at 11332.46,1920.64 h30
  text "MATERIALS AND WORKMANSHIP FOR ALL PCBS" at 12057.46,1920.64 h30
  text "TO MEET OR EXCEED THE REQUIREMENTS OF:" at 12057.46,1822.64 h30
  text "X" at 11683.96,1686.13 h30
  text "ANSI IPC-A-600F CLASS ->" at 11822.96,1686.13 h30
  text "X" at 13462.02,1686.13 h30
  text "2" at 13580.96,1686.14 h30
  text "1" at 13265.96,1684.64 h30
  text "3" at 13934.96,1684.64 h30
  text "X" at 11686.02,1526.64 h30
  text "UL 94V-0" at 11822.96,1526.64 h30
  text "X" at 12498.02,1526.64 h30
  text "RoHS" at 12634.96,1526.64 h30
  text "OTHER" at 13279.36,1526.64 h30
  text "PER ORDER" at 13676.42,1526.64 h30
  text "ADDITIONAL REQUIREMENTS:" at 11332.46,1385.64 h30
  text "MICROSECTION:" at 11407.23,1270.64 h30
  text "YES" at 12312.96,1270.64 h30
  text "REQUIRED" at 13174.46,1114.49 h30
  text "BARE BOARD ELEC. TEST:" at 11407.23,1111.64 h30
  text "NONE" at 12712.96,1111.64 h30
  text "X" at 13047.46,1111.64 h30
  text "PER ORDER" at 13766.46,1111.64 h30
  text "MANUFACTURER'S ID/LOGO:" at 11407.23,954.64 h30
  text "RAIL" at 12872.96,950.35 h30
  text "X" at 13247.46,950.35 h30
  text "METAL" at 13364.77,950.35 h30
  text "SILK" at 13876.46,950.35 h30
  text ".Layer_Name" at 577,-858.49 h30
M11 Gerber Information:
  lines w10: -292,-930.17 6308,-930.17 ; -292,-726.83 6310,-726.83 ; -292,-523.5 -292,-1133.5 3713,-1133.5 6310,-1133.5 6310,-523.5 -291.5,-523.5 -291.5,-1133.5 1284,-1133.5 ; 2173,-1133.5 2173,-523.5 ; 3440,-726.83 3440,-523.5 ; 4280,-726.83 4280,-523.5 ; 4902,-1140 4902,-937.17
  text "ALL ARTWORK VIEWED FROM TOP SIDE" at -228.5,-655.67 h30
  text "BOARD #:" at 2248,-655.67 h30
  text ".PRJ_Number" at 2793.5,-655.67 h30
  text "REV:" at 3638,-655.67 h30
  text ".PCB_Rev" at 3929.5,-655.67 h30
  text "SVN REV:" at 4476,-655.67 h30
  text ".VersionControl_RevNumber" at 4982,-655.67 h30
  text "LAYER NAME =" at -228.5,-858.49 h30
  text "PLOT NAME =" at -228.5,-1064.34 h30
  text ".plot_File_Name" at 577,-1064.34 h30
  text "GENERATED    :" at 2250,-1064.34 h30
  text ".Print_Date" at 3119.5,-1064.34 h30
  text ".Print_Time" at 3848.5,-1064.34 h30
  text "TEXAS INSTRUMENTS" at 5113,-1064.34 h30
M12 Stackup:
  lines w6: 11360,7460 13910,7460 ; 11360,7564.4 13910,7564.4 ; 11300,6975 ccw(c11334,6975) 11334,6941 13936,6941 ccw(c13936,6975) 13970,6975 13970,7681 ccw(c13936,7681) 13936,7715 11334,7715 ccw(c11334,7681) 11300,7681 11300,6975
  text "The Stackup Legend below this is static." at 11605.5,7874.5 h30
  text "If you change the stackup, update the Legend." at 11615.5,7784.5 h30
  text "Layer Stack Up Detail for: Ref_Design.PcbDoc" at 11360,7597.1 h30
  text "Layer" at 11360,7525.4 h30
  text "Gerber" at 12255.81,7525.4 h30
  text "Copper" at 12819.33,7525.4 h30
  text "Dielectric" at 13422.04,7525.4 h30
  text "Name" at 11360,7477.4 h30
  text "Document" at 12255.81,7477.4 h30
  text "Thickness" at 12819.33,7477.4 h30
  text "Material" at 13422.04,7477.4 h30
  text "Top Solder Mask" at 11360,7384.44 h30
  text "(.GTS)" at 12255.81,7384.44 h30
  text "Solder Resist" at 13422.04,7384.44 h30
  text "Top Layer" at 11360,7287.69 h30
  text "(.GTL)" at 12255.81,7287.69 h30
  text "1.4mil" at 12819.33,7287.69 h30
  text "FR-4" at 13422.04,7239.31 h30
  text "Bottom Layer" at 11360,7190.94 h30
  text "(.GBL)" at 12255.81,7190.94 h30
  text "1.4mil" at 12819.33,7190.94 h30
  text "Bottom Solder Mask" at 11360,7094.19 h30
  text "(.GBS)" at 12255.81,7094.19 h30
  text "Solder Resist" at 13422.04,7094.19 h30
  text ".Layer_Name" at 577,-858.49 h30
M13 Component Bodies Top:
  text ".Layer_Name" at 577,-858.49 h30
M14 Component Bodies Bottom:
  text ".Layer_Name" at 577,-858.49 h30
M15 Courtyards Top:
  text ".Layer_Name" at 577,-858.49 h30
M16 Courtyards Bottom:
  text ".Layer_Name" at 577,-858.49 h30
Drill Drawing:
  text ".legend" at 5122.5,725.5 h30
  text "Drill Table" at 5147.5,540.5 h30
  text ".Layer_Name" at 577,-858.49 h30

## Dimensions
0,0 to 3000,0 on M2 Board Dimensions
0,0 to 0,3000 on M2 Board Dimensions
